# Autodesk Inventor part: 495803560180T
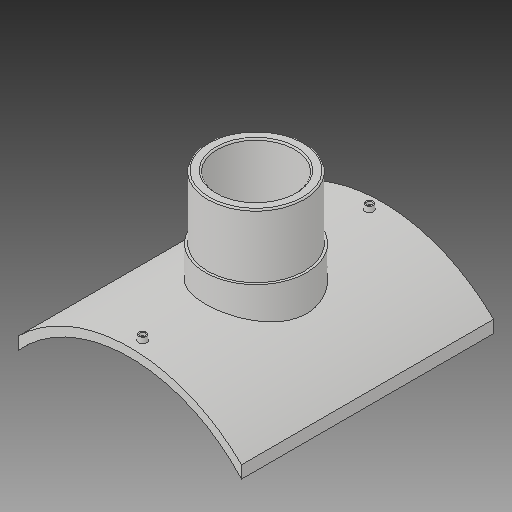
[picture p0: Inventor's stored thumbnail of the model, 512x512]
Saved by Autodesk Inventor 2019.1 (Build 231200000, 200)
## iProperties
Created: 2017-10
Part Number: 495803560180T
Material: Generic
Description: PLASSON BRANCH SADDLE  560x180
Document SubType Name: Modeling
Designer: KIM
Mass: 2754.05 g
Surface Area: 3037.44 cm^2
Volume: 2754.05 cm^3
Density: 1 g/cm^3
Appearance: Default
Author: KIM
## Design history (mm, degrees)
derived "495803.ipt"
feature "Solid1::495803.ipt"
tag "TaggingFeature1"
body "Solid1"
other parameters: "d1" = 16, "d2" = 416, "d4" = 0, "d12" = 305.6, "d13" = 14, "d14" = 211.5, "d16" = 5 deg, "d18" = 4, "d19" = 14, "d20" = 0, "d21" = 3, "d22" = 0, "d23" = 465, "d24" = 189, "d25" = 16, "d26" = 144, "d28" = 0, "d29" = 9.6, "d31" = 0, "d32" = 84.5, "d33" = 0, "d34" = 5.6, "d37" = 118.3, "d38" = 0, "d39" = 2.8, "B_" = 416, "H_" = 169, "x_" = 16, "D_" = 16
